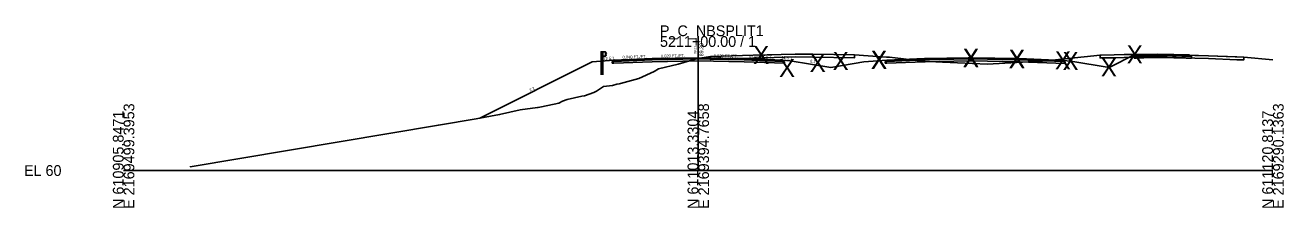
# Model space of a CAD drawing. Extents: x -26 to 1303, y -3010 to 12038.
# Drawn here: x 974.3 to 1302.8, y 6490.3 to 6537.8 of the extents above; entities that cross this region are included whole.
import ezdxf

# ---------------------------------------------------------------- set-up
doc = ezdxf.new("R2010")
doc.units = 0
for name, color, linetype in [('RD_GPK_XS_Cell', 7, 'Continuous'), ('RD_GPK_XS_Text_Node', 7, 'Continuous'), ('RD_PD_Final_TrvlWay', 7, 'Continuous'), ('RD_XS_Base', 7, 'Continuous'), ('RD_XS_ExGround', 7, 'Continuous'), ('RD_XS_ExPaveRet', 7, 'Continuous'), ('RD_XS_GR', 7, 'Continuous'), ('RD_XS_Greenside', 7, 'Continuous'), ('RD_XS_Pave', 7, 'Continuous'), ('RD_XS_PaveOvlay_CP', 7, 'Continuous'), ('RD_XS_TieSlope', 7, 'Continuous'), ('RD_XS_TX_Elev_EX', 7, 'Continuous'), ('RD_XS_TX_Elev_PR', 7, 'Continuous'), ('RD_XS_TX_ShdSlope', 7, 'Continuous'), ('RD_XS_TX_Slope', 7, 'Continuous')]:
    doc.layers.add(name, color=color, linetype=linetype)

msp = doc.modelspace()

# ---------------------------------------------------------------- linework, layer by layer
at = {"layer": 'RD_GPK_XS_Cell'}
for p, q in [((1150, 6500), (1150, 6535)), ((1000, 6500), (1150, 6500)), ((1150, 6500), (1300, 6500))]:
    msp.add_line(p, q, dxfattribs=at)
at = {"layer": 'RD_PD_Final_TrvlWay'}
for p, q in [((1125.11, 6528.52), (1124.61, 6528.48)), ((1124.61, 6528.48), (1124.61, 6524.92)), ((1125.11, 6524.92), (1125.11, 6528.52))]:
    msp.add_line(p, q, dxfattribs=at)
at = {"layer": 'RD_XS_Base'}
for p, q in [((1127.5, 6528.42), (1128, 6528.44)), ((1127.5, 6527.92), (1127.5, 6528.42)), ((1127.5, 6528.42), (1127.5, 6528.42)), ((1128, 6528.44), (1138, 6528.84)), ((1128, 6528.44), (1128, 6528.44)), ((1138, 6528.34), (1128, 6527.94)), ((1138, 6528.84), (1150, 6529.08)), ((1138, 6528.84), (1138, 6528.84)), ((1150, 6528.58), (1138, 6528.34)), ((1138, 6528.34), (1138, 6528.34)), ((1150, 6529.08), (1150, 6529.24)), ((1150, 6529.24), (1150, 6528.58)), ((1150, 6529.08), (1150, 6528.58)), ((1162, 6528.84), (1150, 6529.08)), ((1150, 6529.08), (1150, 6529.08)), ((1150, 6528.58), (1150, 6528.58)), ((1150, 6528.58), (1150, 6528.58)), ((1150, 6528.58), (1162, 6528.34)), ((1172, 6528.44), (1162, 6528.84)), ((1162, 6528.34), (1172.5, 6527.92)), ((1164, 6528.76), (1164, 6528.76)), ((1164, 6528.26), (1164, 6528.26)), ((1172.5, 6528.42), (1172, 6528.44)), ((1172, 6528.44), (1172, 6528.44)), ((1172.5, 6527.92), (1172.5, 6528.42)), ((1172.5, 6528.42), (1172.5, 6528.42)), ((1198.75, 6528.42), (1199.24, 6528.44)), ((1198.75, 6528.41), (1198.75, 6528.42)), ((1198.75, 6527.92), (1198.75, 6528.41)), ((1199.24, 6528.44), (1199.25, 6528.44)), ((1199.25, 6528.44), (1209.01, 6528.83)), ((1209.01, 6528.33), (1199.25, 6527.94)), ((1209.01, 6528.83), (1209.25, 6528.84)), ((1209.25, 6528.34), (1209.01, 6528.33)), ((1209.25, 6528.84), (1220.41, 6529.06)), ((1220.41, 6528.56), (1209.25, 6528.34)), ((1220.41, 6529.06), (1221.25, 6529.08)), ((1221.25, 6528.58), (1220.41, 6528.56)), ((1221.25, 6529.23), (1221.25, 6529.24)), ((1221.25, 6529.24), (1221.25, 6529.21)), ((1221.25, 6529.08), (1221.25, 6529.23)), ((1221.25, 6529.21), (1221.25, 6528.58)), ((1221.25, 6529.08), (1221.25, 6529.06)), ((1221.25, 6529.08), (1221.25, 6529.08)), ((1221.68, 6529.07), (1221.25, 6529.08)), ((1221.25, 6529.08), (1221.25, 6529.08)), ((1221.25, 6529.06), (1221.25, 6528.58)), ((1221.25, 6528.58), (1221.68, 6528.57)), ((1233.25, 6528.84), (1221.68, 6529.07)), ((1221.68, 6528.57), (1233.25, 6528.34)), ((1233.75, 6528.82), (1233.25, 6528.84)), ((1233.25, 6528.34), (1233.77, 6528.32)), ((1245.25, 6528.36), (1233.75, 6528.82)), ((1233.77, 6528.32), (1245.75, 6527.84)), ((1245.27, 6528.36), (1245.25, 6528.36)), ((1245.75, 6528.34), (1245.27, 6528.36)), ((1245.75, 6528.32), (1245.75, 6528.34)), ((1245.75, 6527.84), (1245.75, 6528.32)), ((1263.76, 6529.77), (1264.26, 6529.78)), ((1263.76, 6529.27), (1263.76, 6529.77)), ((1264.26, 6529.28), (1263.76, 6529.27)), ((1264.26, 6529.78), (1266.26, 6529.82)), ((1266.26, 6529.32), (1264.26, 6529.28)), ((1266.26, 6529.82), (1271.26, 6529.92)), ((1271.26, 6529.42), (1266.26, 6529.32)), ((1271.26, 6529.99), (1271.26, 6530.08)), ((1271.26, 6530.08), (1271.26, 6529.71)), ((1271.26, 6529.92), (1271.26, 6529.99)), ((1274.1, 6529.86), (1271.26, 6529.92)), ((1271.26, 6529.92), (1271.26, 6529.42)), ((1271.26, 6529.71), (1271.26, 6529.42)), ((1271.26, 6529.42), (1274.1, 6529.36)), ((1276.26, 6529.82), (1274.1, 6529.86)), ((1274.1, 6529.36), (1276.26, 6529.32)), ((1277.11, 6529.8), (1276.26, 6529.82)), ((1276.26, 6529.32), (1277.32, 6529.3)), ((1278.26, 6529.78), (1277.11, 6529.8)), ((1277.32, 6529.3), (1278.76, 6529.27)), ((1278.55, 6529.77), (1278.26, 6529.78)), ((1278.76, 6529.77), (1278.55, 6529.77)), ((1278.76, 6529.48), (1278.76, 6529.77)), ((1278.76, 6529.27), (1278.76, 6529.48)), ((1128, 6527.94), (1127.5, 6527.92)), ((1127.5, 6527.92), (1127.5, 6527.92)), ((1127.5, 6527.92), (1127.5, 6527.92)), ((1128, 6527.94), (1128, 6527.94)), ((1172.5, 6527.92), (1172.5, 6527.92)), ((1172.5, 6527.92), (1172.5, 6527.92)), ((1199.24, 6527.94), (1198.75, 6527.92)), ((1199.25, 6527.94), (1199.24, 6527.94))]:
    msp.add_line(p, q, dxfattribs=at)
at = {"layer": 'RD_XS_ExGround'}
msp.add_lwpolyline([(1017.35, 6500.97), (1017.37, 6501.01), (1082.15, 6511.82), (1092.04, 6513.47), (1098.13, 6514.57), (1103.49, 6515.77), (1108.04, 6516.4), (1108.07, 6516.41), (1108.24, 6516.44), (1109.08, 6516.6), (1113.63, 6517.54), (1114.58, 6518.09), (1115.75, 6518.49), (1119.63, 6519.35), (1120.26, 6519.45), (1122.72, 6520.34), (1123.43, 6520.65), (1125.23, 6521.86), (1127.58, 6522.19), (1128.74, 6522.47), (1129.36, 6522.56), (1129.72, 6522.69), (1134.49, 6523.97), (1138.45, 6525.83), (1139.6, 6526.53), (1144.72, 6527.73), (1149.83, 6529.19), (1153.18, 6529.66), (1164.3, 6530.02), (1175.32, 6530.35), (1179.92, 6530.29), (1190.82, 6530.12), (1199.11, 6529.55), (1199.87, 6529.5), (1201.36, 6529.33), (1208.6, 6528.49), (1213.73, 6528.24), (1225.47, 6527.67), (1239.11, 6528.46), (1239.65, 6528.5), (1239.83, 6528.5), (1240.73, 6528.6), (1254.87, 6530.07), (1258.54, 6530.13), (1269.95, 6530.32), (1283.2, 6529.89), (1292.39, 6529.55), (1300, 6528.84)], dxfattribs=at)
at = {"layer": 'RD_XS_ExPaveRet'}
for p, q in [((1164.3, 6530.02), (1153.18, 6529.66)), ((1292.39, 6529.55), (1290.6, 6529.62))]:
    msp.add_line(p, q, dxfattribs=at)
for points in [[(1190.82, 6530.12), (1190.82, 6529.37), (1190.82, 6529.37), (1190.82, 6529.37), (1179.92, 6529.54), (1179.92, 6529.54), (1175.32, 6529.6), (1175.32, 6529.6), (1175.32, 6529.6), (1164.3, 6529.27), (1164.3, 6529.27), (1153.18, 6528.91), (1153.18, 6528.91), (1153.18, 6529.66), (1164.3, 6530.02), (1164.3, 6530.02), (1175.32, 6530.35), (1175.32, 6530.35), (1175.32, 6530.35), (1179.92, 6530.29), (1179.92, 6530.29), (1190.82, 6530.12), (1190.82, 6530.12)], [(1153.18, 6529.66), (1153.18, 6528.91), (1164.3, 6529.27), (1175.32, 6529.6), (1179.92, 6529.54), (1190.82, 6529.37), (1190.82, 6530.12), (1179.92, 6530.29), (1175.32, 6530.35), (1164.3, 6530.02)], [(1283.2, 6529.89), (1279.63, 6530), (1269.95, 6530.32), (1261.18, 6530.18), (1258.54, 6530.13), (1255.2, 6530.08), (1254.87, 6530.07), (1254.87, 6529.46), (1254.87, 6529.32), (1255.2, 6529.33), (1258.54, 6529.38), (1261.18, 6529.43), (1269.95, 6529.57), (1279.63, 6529.25), (1283.2, 6529.14), (1290.6, 6528.87), (1292.39, 6528.8), (1292.39, 6529.36), (1292.39, 6529.55), (1290.6, 6529.62), (1283.2, 6529.89)], [(1258.54, 6530.13), (1255.2, 6530.08), (1254.87, 6530.07)], [(1254.87, 6530.07), (1254.87, 6529.46), (1254.87, 6529.32), (1255.2, 6529.33), (1258.54, 6529.38), (1261.18, 6529.43), (1269.95, 6529.57), (1279.63, 6529.25), (1283.2, 6529.14), (1290.6, 6528.87), (1292.39, 6528.8), (1292.39, 6529.36), (1292.39, 6529.55)], [(1269.95, 6530.32), (1261.18, 6530.18), (1258.54, 6530.13)], [(1290.6, 6529.62), (1283.2, 6529.89), (1279.63, 6530), (1269.95, 6530.32)]]:
    msp.add_lwpolyline(points, dxfattribs=at)
at = {"layer": 'RD_XS_GR'}
for points in [[(1125.11, 6530.92), (1125.11, 6528.52), (1124.61, 6528.48), (1124.61, 6530.92), (1124.86, 6530.92), (1125.11, 6530.92)], [(1125.77, 6530.92), (1125.77, 6529.75), (1125.11, 6529.75), (1125.11, 6530.92), (1125.77, 6530.92)], [(1126.04, 6530.63), (1125.77, 6530.92), (1125.77, 6529.75), (1125.77, 6529.75), (1125.77, 6529.75), (1126.04, 6530.04), (1126.04, 6530.04), (1125.77, 6530.34), (1125.77, 6530.34), (1126.04, 6530.63), (1126.04, 6530.63)]]:
    msp.add_lwpolyline(points, dxfattribs=at)
at = {"layer": 'RD_XS_Greenside'}
for p, q in [((1122.29, 6528.3), (1092.96, 6513.63)), ((1174, 6528.59), (1184.58, 6526.83)), ((1193.25, 6528.28), (1184.58, 6526.83)), ((1247.25, 6528.52), (1257.25, 6526.85)), ((1257.25, 6526.85), (1263.99, 6530.22))]:
    msp.add_line(p, q, dxfattribs=at)
at = {"layer": 'RD_XS_Pave'}
for p, q in [((1138, 6529.15), (1128, 6528.75)), ((1138, 6529), (1128, 6528.6)), ((1128, 6528.6), (1138, 6529)), ((1128, 6528.44), (1138, 6528.84)), ((1128, 6528.75), (1128, 6528.75)), ((1128, 6528.75), (1128, 6528.6)), ((1128, 6528.6), (1128, 6528.6)), ((1128, 6528.6), (1128, 6528.44)), ((1128, 6528.6), (1128, 6528.6)), ((1128, 6528.6), (1128, 6528.6)), ((1128, 6528.44), (1128, 6528.44)), ((1128, 6528.44), (1128, 6528.44)), ((1150, 6529.39), (1138, 6529.15)), ((1150, 6529.24), (1138, 6529)), ((1138, 6529), (1150, 6529.24)), ((1138, 6529.15), (1138, 6529.15)), ((1138, 6528.84), (1150, 6529.08)), ((1138, 6529), (1138, 6529)), ((1138, 6529), (1138, 6529)), ((1138, 6528.84), (1138, 6528.84)), ((1162, 6529.15), (1150, 6529.39)), ((1150, 6529.08), (1150, 6529.24)), ((1150, 6529.24), (1162, 6529)), ((1162, 6529), (1150, 6529.24)), ((1150, 6529.24), (1150, 6529.08)), ((1150, 6529.08), (1150, 6529.08)), ((1150, 6529.08), (1150, 6529.08)), ((1150, 6529.08), (1162, 6528.84)), ((1172, 6528.75), (1162, 6529.15)), ((1162, 6529), (1172, 6528.6)), ((1172, 6528.6), (1162, 6529)), ((1162, 6528.84), (1172, 6528.44)), ((1164, 6529.07), (1164, 6529.07)), ((1164, 6528.92), (1164, 6528.92)), ((1164, 6528.92), (1164, 6528.92)), ((1164, 6528.76), (1164, 6528.76)), ((1172, 6528.6), (1172, 6528.75)), ((1172, 6528.75), (1172, 6528.75)), ((1172, 6528.6), (1172, 6528.6)), ((1172, 6528.6), (1172, 6528.6)), ((1172, 6528.44), (1172, 6528.6)), ((1172, 6528.6), (1172, 6528.6)), ((1172, 6528.44), (1172, 6528.44)), ((1172, 6528.44), (1172, 6528.44)), ((1209.01, 6529.15), (1199.25, 6528.76)), ((1209.01, 6528.99), (1199.25, 6528.6)), ((1199.25, 6528.6), (1209.01, 6528.99)), ((1199.25, 6528.44), (1209.01, 6528.83)), ((1199.25, 6528.76), (1199.25, 6528.75)), ((1199.25, 6528.75), (1199.25, 6528.6)), ((1199.25, 6528.6), (1199.25, 6528.59)), ((1199.25, 6528.59), (1199.25, 6528.44)), ((1209.25, 6529.16), (1209.01, 6529.15)), ((1209.25, 6529), (1209.01, 6528.99)), ((1209.01, 6528.99), (1209.25, 6529)), ((1209.01, 6528.83), (1209.25, 6528.84)), ((1220.41, 6529.38), (1209.25, 6529.16)), ((1220.41, 6529.22), (1209.25, 6529)), ((1209.25, 6529), (1220.41, 6529.22)), ((1209.25, 6528.84), (1220.41, 6529.06)), ((1221.25, 6529.4), (1220.41, 6529.38)), ((1221.25, 6529.24), (1220.41, 6529.22)), ((1220.41, 6529.22), (1221.25, 6529.24)), ((1220.41, 6529.06), (1221.25, 6529.08)), ((1221.68, 6529.39), (1221.25, 6529.4)), ((1221.25, 6529.23), (1221.25, 6529.24)), ((1221.25, 6529.24), (1221.68, 6529.23)), ((1221.68, 6529.23), (1221.25, 6529.24)), ((1221.25, 6529.24), (1221.25, 6529.24)), ((1221.25, 6529.24), (1221.25, 6529.24)), ((1221.25, 6529.24), (1221.25, 6529.23)), ((1221.25, 6529.08), (1221.25, 6529.23)), ((1221.25, 6529.23), (1221.25, 6529.08)), ((1221.25, 6529.08), (1221.25, 6529.08)), ((1221.25, 6529.08), (1221.25, 6529.08)), ((1221.25, 6529.08), (1221.68, 6529.07)), ((1233.25, 6529.16), (1221.68, 6529.39)), ((1221.68, 6529.23), (1233.25, 6529)), ((1233.25, 6529), (1221.68, 6529.23)), ((1221.68, 6529.07), (1233.25, 6528.84)), ((1233.75, 6529.14), (1233.25, 6529.16)), ((1233.25, 6529), (1233.75, 6528.98)), ((1233.75, 6528.98), (1233.25, 6529)), ((1233.25, 6528.84), (1233.75, 6528.82)), ((1245.25, 6528.68), (1233.75, 6529.14)), ((1233.75, 6528.98), (1245.25, 6528.52)), ((1245.25, 6528.52), (1233.75, 6528.98)), ((1233.75, 6528.82), (1245.25, 6528.36)), ((1245.25, 6528.67), (1245.25, 6528.68)), ((1245.25, 6528.52), (1245.25, 6528.67)), ((1245.25, 6528.51), (1245.25, 6528.52)), ((1245.25, 6528.36), (1245.25, 6528.51)), ((1265.17, 6530.11), (1264.26, 6530.1)), ((1264.26, 6530.1), (1264.26, 6530.02)), ((1264.26, 6530.02), (1264.26, 6529.94)), ((1266.26, 6529.98), (1264.26, 6529.94)), ((1264.26, 6529.94), (1265.17, 6529.96)), ((1264.26, 6529.94), (1264.26, 6529.78)), ((1264.26, 6529.78), (1266.26, 6529.82)), ((1266.26, 6530.14), (1265.17, 6530.11)), ((1265.17, 6529.96), (1266.26, 6529.98)), ((1269.03, 6530.19), (1266.26, 6530.14)), ((1271.26, 6530.08), (1266.26, 6529.98)), ((1266.26, 6529.98), (1269.03, 6530.03)), ((1266.26, 6529.82), (1271.26, 6529.92)), ((1271.26, 6530.24), (1269.03, 6530.19)), ((1269.03, 6530.03), (1271.26, 6530.08)), ((1274.1, 6530.18), (1271.26, 6530.24)), ((1271.26, 6530.08), (1274.1, 6530.02)), ((1276.26, 6529.98), (1271.26, 6530.08)), ((1271.26, 6530.08), (1271.26, 6529.92)), ((1271.26, 6529.92), (1271.26, 6530.08)), ((1271.26, 6529.92), (1276.26, 6529.82)), ((1276.26, 6530.14), (1274.1, 6530.18)), ((1274.1, 6530.02), (1276.26, 6529.98)), ((1277.11, 6530.12), (1276.26, 6530.14)), ((1276.26, 6529.98), (1277.11, 6529.96)), ((1278.26, 6529.94), (1276.26, 6529.98)), ((1276.26, 6529.82), (1278.26, 6529.78)), ((1278.26, 6530.1), (1277.11, 6530.12)), ((1277.11, 6529.96), (1278.26, 6529.94)), ((1278.26, 6530), (1278.26, 6530.1)), ((1278.26, 6529.94), (1278.26, 6530)), ((1278.26, 6529.78), (1278.26, 6529.94))]:
    msp.add_line(p, q, dxfattribs=at)
at = {"layer": 'RD_XS_PaveOvlay_CP'}
for p, q in [((1128, 6528.75), (1138, 6529.15)), ((1138, 6529.15), (1150, 6529.39)), ((1150, 6529.39), (1162, 6529.15)), ((1162, 6529.15), (1172, 6528.75)), ((1209.01, 6529.15), (1199.25, 6528.76)), ((1209.25, 6529.16), (1209.01, 6529.15)), ((1220.41, 6529.38), (1209.25, 6529.16)), ((1221.25, 6529.4), (1220.41, 6529.38)), ((1221.68, 6529.39), (1221.25, 6529.4)), ((1233.25, 6529.16), (1221.68, 6529.39)), ((1233.75, 6529.14), (1233.25, 6529.16)), ((1245.25, 6528.68), (1233.75, 6529.14)), ((1264.26, 6530.1), (1266.26, 6530.14)), ((1266.26, 6530.14), (1271.26, 6530.24)), ((1271.26, 6530.24), (1276.26, 6530.14)), ((1276.26, 6530.14), (1278.26, 6530.1))]:
    msp.add_line(p, q, dxfattribs=at)
at = {"layer": 'RD_XS_TieSlope'}
for p, q in [((1128, 6528.75), (1122.29, 6528.3)), ((1172, 6528.75), (1174, 6528.59)), ((1199.25, 6528.76), (1193.25, 6528.28)), ((1245.25, 6528.68), (1247.25, 6528.52))]:
    msp.add_line(p, q, dxfattribs=at)

# ---------------------------------------------------------------- texts
at = {"layer": 'RD_GPK_XS_Cell'}
for s, p in [('P_C_NBSPLIT1', (1140, 6535)), ('5211+00.00 / 1', (1140, 6532.2)), ('EL 60', (974, 6498.6))]:
    msp.add_text(s, height=2.8, dxfattribs=at).set_placement(p)
for s, p in [('N 610905.8471', (1000, 6490)), ('E 2169499.3953', (1002.8, 6490)), ('N 611013.3304', (1150, 6490)), ('E 2169394.7658', (1152.8, 6490)), ('N 611120.8137', (1300, 6490)), ('E 2169290.1363', (1302.8, 6490))]:
    msp.add_text(s, height=2.8, rotation=90, dxfattribs=at).set_placement(p)
at = {"layer": 'RD_GPK_XS_Text_Node'}
for p in [(1164.32, 6527.74), (1195.08, 6526.57), (1219.08, 6527.05), (1219.08, 6526.89), (1231.08, 6526.81), (1231.08, 6526.65), (1261.83, 6527.88), (1171.08, 6524.36), (1179.08, 6525.69), (1185.08, 6526.17), (1195.08, 6526.41), (1243.08, 6526.33), (1245.08, 6526.17), (1255.08, 6524.51)]:
    msp.add_text('X', height=4.69, dxfattribs=at).set_placement(p)
at = {"layer": 'RD_XS_TX_Elev_EX'}
msp.add_text('89.21', height=0.6, rotation=90, dxfattribs=at).set_placement((1149.46, 6530.36))
at = {"layer": 'RD_XS_TX_Elev_PR'}
msp.add_text('89.39', height=1, rotation=90, dxfattribs=at).set_placement((1151.31, 6529.75))
at = {"layer": 'RD_XS_TX_ShdSlope'}
for rotation, p in [(4.5739, (1125.26, 6528.73)), (355.4261, (1171.67, 6529.11))]:
    msp.add_text('12.5:1', height=0.75, rotation=rotation, dxfattribs=at).set_placement(p)
at = {"layer": 'RD_XS_TX_Slope'}
for s, rotation, p in [('0.040 FT./FT.', 2.2906, (1130.25, 6529.13)), ('0.020 FT./FT.', 1.1458, (1140.25, 6529.46)), ('0.020 FT./FT.', 358.8542, (1154.04, 6529.53)), ('0.040 FT./FT.', 357.7094, (1163.26, 6529.36)), ('6:1', 350.5377, (1179.13, 6528.17)), ('2:1', 26.5651, (1106.13, 6520.56))]:
    msp.add_text(s, height=0.75, rotation=rotation, dxfattribs=at).set_placement(p)

doc.saveas('drawing.dxf')
